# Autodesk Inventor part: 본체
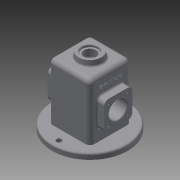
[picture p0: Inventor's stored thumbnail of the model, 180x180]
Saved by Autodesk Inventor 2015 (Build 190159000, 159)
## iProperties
Created: 2021-08
Part Number: 본체
Material: 일반
Document SubType Name: Modeling
Designer: 1048888
Density: 1 g/cm^3
Appearance: 기본값
Author: 1048888
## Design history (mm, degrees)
sketch "스케치1"
  geometry: L1 (-37, -37)-(37, -37); L2 (37, -37)-(37, 37); L3 (37, 37)-(-37, 37); L4 (-37, 37)-(-37, -37); L5 (-37, -37)-(37, 37); L6 (37, -37)-(-37, 37); 1 further point
  constraints: 12 end point, 2 midpoint, 2 parallel, 1 horizontal, 1 perpendicular
  dimensions: "d0" = 74 distance of L1.end L2.end; "d1" = 74 distance of L1.start L1.end
extrude "돌출1" new body sketch "스케치1" distance "d2" = 110; taper "d3" = 0 deg
feature "쉘1" dims "d4" = 5
sketch "스케치2"
  geometry: L1 (37, -37)-(-37, -37) reference; L2 (37, 37)-(37, -37) reference; L3 (-37, 37)-(37, 37) reference; L4 (-37, -37)-(-37, 37) reference; C1 r 67 at (0, 0); 1 further point
  constraints: 1 centre point, 1 coincident
  dimensions: "d5" = 134 diameter of C1
extrude "돌출2" join sketch "스케치2" distance "d6" = 10; taper "d7" = 0 deg
sketch "스케치3"
  geometry: L1 (100, 0)-(0, 0) reference; L2 (80, 62)-(30, 62); L3 (30, 62)-(30, 12); L4 (30, 12)-(80, 12); L5 (80, 12)-(80, 62); L6 (80, 62)-(30, 12); L7 (30, 62)-(80, 12); L8 (110, 104)-(110, -30) reference; 2 further points
  constraints: 12 end point, 2 midpoint, 2 parallel, 1 horizontal, 1 perpendicular
  dimensions: "d8" = 55 distance from line of L8 point (55, 37); "d9" = 50 distance of L2.start L2.end; "d10" = 50 distance of L2.end L3.end; "d11" = 12 distance between parallel lines of L1 L4
extrude "돌출3" join sketch "스케치3" distance "d12" = 87; taper "d14" = 0 deg; dims "d13" = 13, "d15" = 0
sketch "스케치4"
  geometry: L1 (30, 12)-(80, 62); C1 r 16 at (55, 37); 1 further point
  constraints: 2 end point, 1 centre point, 1 midpoint
  dimensions: "d16" = 32 diameter of C1
extrude "돌출4" cut sketch "스케치4" stored distance "d17" = 87; taper "d18" = 0 deg
sketch "스케치5"
  geometry: C1 r 20 at (0, 0); 1 further point
  constraints: 1 centre point, 1 coincident
  dimensions: "d19" = 40 diameter of C1
extrude "돌출5" join sketch "스케치5" distance "d20" = 10; taper "d21" = 0 deg
sketch "스케치6"
  geometry: C1 r 20 at (0, 0) reference
hole "구멍1" sketch "스케치6" at (0, 0) diameter "d22" = 21; stored, may be unused: countersink angle "d26" = 90 deg, drill point angle "d28" = 118 deg; dims "d23" = 6, "d24" = 28, "d25" = 4, "d27" = 8
fillet "모깎기1" dims "d29" = 8
fillet "모깎기2" dims "d30" = 8
sketch "스케치7"
  geometry: A1 r 8 centre (72, 54) between (80, 54) and (72, 62) reference; A2 r 8 centre (38, 54) between (38, 62) and (30, 54) reference; A3 r 8 centre (38, 20) between (30, 20) and (38, 12) reference; A4 r 8 centre (72, 20) between (72, 12) and (80, 20) reference; 1 further point
hole "구멍2" sketch "스케치7" diameter "d31" = 3.242; stored, may be unused: countersink angle "d35" = 90 deg, drill point angle "d37" = 118 deg; dims "d32" = 8, "d33" = 4, "d34" = 2, "d36" = 10
sketch "스케치9"
  geometry: C1 r 67 at (0, 0) reference; 1 further point
  constraints: 1 vertical alignment
  dimensions: "d38" = 55 distance of C1.centre point (0, 55)
hole "구멍3" sketch "스케치9" at (0, 55) diameter "d39" = 9; stored, may be unused: countersink angle "d43" = 90 deg, drill point angle "d45" = 118 deg; dims "d40" = 8, "d41" = 4, "d42" = 2, "d44" = 10
fillet "모깎기3" dims "d46" = 8
sketch "스케치10"
  geometry: L1 (-25, 25)-(25, 25); L2 (25, 25)-(25, -25); L3 (25, -25)-(-25, -25); L4 (-25, -25)-(-25, 25); L5 (-25, 25)-(25, -25); L6 (25, 25)-(-25, -25); C1 r 67 at (0, 0) reference
  constraints: 12 end point, 2 midpoint, 2 parallel, 1 horizontal, 1 perpendicular
  dimensions: "d47" = 50 distance of L2.end L3.end; "d48" = 50 distance of L1.end L2.end
extrude "돌출6" cut sketch "스케치10" distance "d49" = 100; taper "d50" = 0 deg
feature "면 기울기1" dims angle "d51" = 20 deg
feature "면 기울기2" dims angle "d52" = 20 deg
fillet "모깎기4" dims "d53" = 8
fillet "모깎기5" dims "d54" = 3
fillet "모깎기6" dims "d55" = 3
fillet "모깎기7" dims "d56" = 3
chamfer "모따기1" distance "d57" = 1; stored, may be unused: second distance "d58" = 2, angle "d59" = 45 deg
sketch "스케치11"
  geometry: L1 (-92, -8)-(0, -8) reference; L2 (-110, 49)-(-110, 9) reference; 2 further points
  constraints: 1 other
  dimensions: "d60" = 37 distance from line of L1 point (-82, 29); "d61" = 28 distance from line of point (-82, 29) L2
feature "엠보싱1" sketch "스케치11" dims "d0" = 74, "d1" = 74, "d62" = 0.5, "d63" = 0
fillet "모깎기9" dims "d65" = 3
fillet "모깎기10" dims "d66" = 3
feature "면 기울기4" dims angle "d69" = 6 deg
fillet "모깎기12" dims "d70" = 3
node "솔리드1"
mirror "대칭1"
mirror "대칭2"
